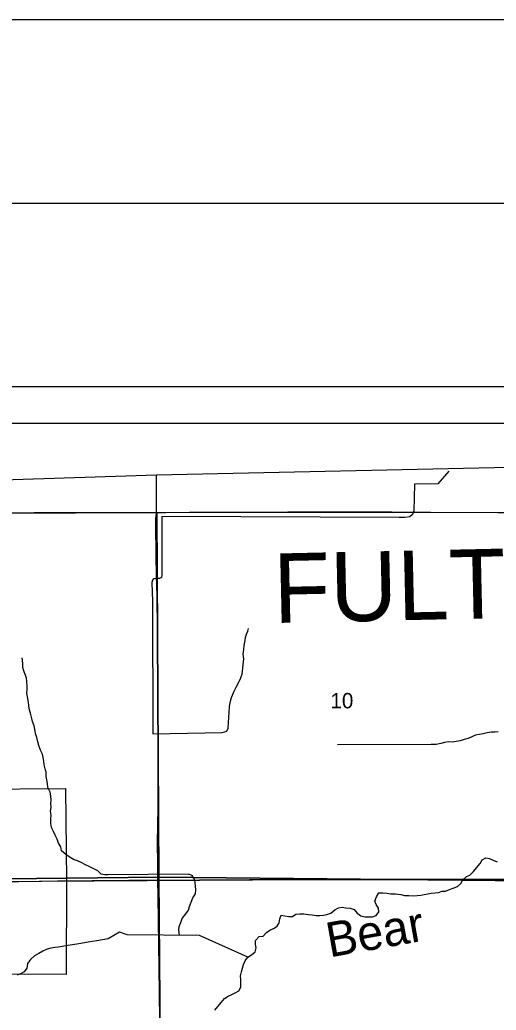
# Model space of a CAD drawing. Extents: x 0 to 34, y 0 to 22.
# Drawn here: x 4.098 to 5.396, y 19.3 to 22 of the extents above; entities that cross this region are included whole.
import ezdxf

# ---------------------------------------------------------------- set-up
doc = ezdxf.new("R2010")
doc.units = 0
for name, color, linetype in [('Default', 7, 'Continuous'), ('GM_X_Corporation', 7, 'Continuous'), ('GM_X_County_Text', 7, 'Continuous'), ('GM_X_Minor_River', 7, 'Continuous'), ('GM_X_Minor_River_Text', 7, 'Continuous'), ('GM_X_Rail_Line', 7, 'Continuous'), ('GM_X_Section', 7, 'Continuous'), ('GM_X_Section_Text', 7, 'Continuous'), ('GM_X_State_Route', 7, 'Continuous'), ('GM_X_Township_Road', 7, 'Continuous'), ('SH_Border', 7, 'Continuous'), ('SH_Cut_Line', 7, 'Continuous'), ('SH_Data', 7, 'Continuous')]:
    doc.layers.add(name, color=color, linetype=linetype)

msp = doc.modelspace()

# ---------------------------------------------------------------- linework, layer by layer
at = {"layer": 'Default'}
msp.add_lwpolyline([(5.4741, 20.7803), (4.4698, 20.7584), (3.7151, 20.7343)], dxfattribs=at)
at = {"layer": 'GM_X_Corporation'}
msp.add_lwpolyline([(3.155, 19.3995), (3.1598, 19.65), (3.0434, 19.6498), (3.0413, 19.9196), (3.1522, 19.9187), (3.151, 20.1523), (3.4671, 20.153), (3.72, 20.1538), (3.9709, 20.1548), (3.9717, 19.9024), (4.2217, 19.9047), (4.2244, 19.6529), (4.2237, 19.397), (3.7274, 19.3997), (3.2857, 19.3997)], close=True, dxfattribs=at)
at = {"layer": 'GM_X_Minor_River'}
for points in [[(5.2672, 20.7693), (5.2366, 20.7353), (5.1729, 20.7341), (5.171, 20.6616), (5.1678, 20.6514), (5.1609, 20.6446), (5.1469, 20.6436), (5.1313, 20.6434), (4.4846, 20.6459), (4.4848, 20.4862), (4.4835, 20.4794), (4.4786, 20.4771), (4.4721, 20.4764), (4.4619, 20.4758), (4.4588, 20.4724), (4.4569, 20.466), (4.4589, 20.4143), (4.4602, 20.0538), (4.6487, 20.0573), (4.6616, 20.061), (4.6651, 20.0685), (4.6691, 20.1266), (4.6708, 20.1387), (4.6744, 20.1527), (4.6821, 20.1701), (4.6876, 20.181), (4.6984, 20.2014), (4.7031, 20.2162), (4.7061, 20.2416), (4.7078, 20.2578), (4.7064, 20.2704), (4.7077, 20.2837), (4.7093, 20.2946), (4.7113, 20.3079), (4.713, 20.3159), (4.7157, 20.3249), (4.7188, 20.3329), (4.7208, 20.3404)], [(4.3373, 19.6688), (4.3294, 19.6688), (4.3195, 19.6712), (4.3098, 19.6796), (4.2977, 19.6866), (4.2868, 19.692), (4.2762, 19.6959), (4.2649, 19.7024), (4.2551, 19.7067), (4.2453, 19.7102), (4.2347, 19.716), (4.2231, 19.7241), (4.2114, 19.7345), (4.2089, 19.7451), (4.2029, 19.755), (4.1996, 19.7661), (4.1937, 19.7775), (4.1896, 19.7874), (4.1837, 19.7977), (4.1823, 19.8087), (4.182, 19.8209), (4.1829, 19.8315), (4.1811, 19.8425), (4.1828, 19.8528), (4.1821, 19.863), (4.1826, 19.8725), (4.182, 19.8843), (4.1806, 19.8941), (4.1743, 19.9075), (4.1729, 19.9181), (4.1711, 19.928), (4.1693, 19.9375), (4.169, 19.9485), (4.1665, 19.958), (4.1643, 19.9687), (4.1633, 19.9786), (4.1612, 19.9888), (4.159, 19.9983), (4.1542, 20.009), (4.1498, 20.0212), (4.1468, 20.0315), (4.1443, 20.0433), (4.1407, 20.0547), (4.1385, 20.0661), (4.1363, 20.0756), (4.1323, 20.0874), (4.129, 20.0992), (4.1265, 20.1095), (4.1232, 20.1216), (4.1222, 20.1319), (4.12, 20.1441), (4.1183, 20.1543), (4.1168, 20.1642), (4.1173, 20.1741), (4.1174, 20.1839), (4.1168, 20.1949), (4.1154, 20.2056), (4.1121, 20.2151), (4.1084, 20.225), (4.1059, 20.2345), (4.1056, 20.244), (4.105, 20.2539), (4.1043, 20.2603)], [(5.4015, 20.0586), (5.392, 20.058), (5.3822, 20.0577), (5.3716, 20.0559), (5.3605, 20.0537), (5.3495, 20.0516), (5.3393, 20.0498), (5.3297, 20.0453), (5.3191, 20.0409), (5.3088, 20.0379), (5.2978, 20.0342), (5.2871, 20.0328), (5.2754, 20.0303), (5.2648, 20.0315), (5.2549, 20.0294), (5.2454, 20.0268), (5.2324, 20.0242), (5.2184, 20.0244)], [(5.2184, 20.0244), (4.9633, 20.0235)], [(4.7073, 19.4241), (4.7116, 19.4343), (4.7193, 19.4445), (4.7288, 19.4508), (4.7388, 19.4591), (4.7415, 19.4697), (4.7401, 19.4803), (4.7402, 19.4902), (4.7498, 19.5011), (4.7605, 19.5018), (4.7697, 19.5119), (4.7792, 19.5183), (4.7887, 19.5224), (4.7987, 19.5287), (4.8048, 19.5385), (4.8061, 19.5491), (4.8096, 19.559), (4.8194, 19.5574), (4.8297, 19.555), (4.8403, 19.5556), (4.8498, 19.562), (4.8608, 19.5626), (4.8714, 19.5622), (4.8839, 19.5605), (4.8941, 19.5597), (4.9051, 19.5584), (4.915, 19.5579), (4.9248, 19.559), (4.9347, 19.5604), (4.9454, 19.5648), (4.9557, 19.5731), (4.9664, 19.5787), (4.9759, 19.5809), (4.9861, 19.5793), (4.9975, 19.5784), (5.0084, 19.5741), (5.0166, 19.5642), (5.0272, 19.5572), (5.0374, 19.5548), (5.0484, 19.554), (5.059, 19.5546), (5.0689, 19.5579), (5.0758, 19.5677), (5.0755, 19.578), (5.0688, 19.5879), (5.0648, 19.5975), (5.0698, 19.6092), (5.0756, 19.6201), (5.087, 19.6196), (5.098, 19.6191), (5.109, 19.6171), (5.1211, 19.6174), (5.1355, 19.615), (5.1457, 19.613), (5.1574, 19.6125), (5.1696, 19.612), (5.1809, 19.6123), (5.1904, 19.6133), (5.1999, 19.6155), (5.2094, 19.6173), (5.2189, 19.6187), (5.2295, 19.6197), (5.239, 19.6204), (5.2485, 19.6245), (5.258, 19.6248), (5.2683, 19.6292), (5.279, 19.6329), (5.29, 19.6374), (5.2999, 19.6452), (5.305, 19.6551), (5.3145, 19.6641), (5.3241, 19.6678), (5.3337, 19.6783), (5.3417, 19.6881), (5.3517, 19.6998), (5.3575, 19.7103), (5.3674, 19.7155), (5.3773, 19.7139), (5.3878, 19.7085), (5.3988, 19.7046)], [(4.5576, 19.6711), (4.3373, 19.6688)], [(4.5331, 19.5044), (4.5305, 19.5181), (4.5322, 19.5283), (4.5364, 19.5389), (4.5404, 19.5495), (4.55, 19.5623), (4.5569, 19.5725), (4.5604, 19.5827), (4.5647, 19.594), (4.5694, 19.6065), (4.576, 19.6174), (4.5772, 19.6277), (4.5762, 19.6379), (4.5752, 19.6478), (4.5738, 19.6573), (4.5674, 19.6668), (4.5576, 19.6711), (4.5584, 19.6707)], [(4.7193, 19.4445), (4.5876, 19.5038), (4.3901, 19.5058), (4.369, 19.5124), (4.3381, 19.4941), (4.3073, 19.4888), (4.2834, 19.4852), (4.2583, 19.4805), (4.2412, 19.478), (4.2287, 19.4759)], [(4.2287, 19.4759), (4.2021, 19.4719), (4.1926, 19.4709), (4.182, 19.4691), (4.1725, 19.4665), (4.1603, 19.461), (4.1492, 19.4543), (4.1374, 19.4479), (4.1271, 19.4378), (4.1186, 19.4268), (4.1166, 19.4147), (4.1093, 19.4046), (4.0997, 19.399), (4.0902, 19.3956)], [(4.6286, 19.2996), (4.6382, 19.3109), (4.6459, 19.3207), (4.6551, 19.3316), (4.6651, 19.3384), (4.6753, 19.3428), (4.6849, 19.3469), (4.6948, 19.3525), (4.7002, 19.3627), (4.6999, 19.3733), (4.6997, 19.3832), (4.699, 19.3938), (4.7018, 19.4044), (4.7042, 19.4143), (4.7073, 19.4241)]]:
    msp.add_lwpolyline(points, dxfattribs=at)
at = {"layer": 'GM_X_Rail_Line'}
msp.add_lwpolyline([(2.1, 19.6449), (2.4687, 19.6463), (3.2362, 19.6474), (3.7244, 19.6491), (5.0197, 19.6574), (5.4852, 19.6574), (5.5146, 19.6675), (5.5588, 19.7034), (6.1514, 20.0969), (6.291, 20.193), (6.3333, 20.2132), (6.3747, 20.2169), (6.4833, 20.2279), (7.4795, 20.3149), (8.1518, 20.3773), (8.7379, 20.4271), (8.9, 20.4441)], dxfattribs=at)
at = {"layer": 'GM_X_Section'}
for points in [[(3.4668, 20.6546), (4.4712, 20.6576), (4.4763, 19.663), (3.4763, 19.6515)], [(4.4712, 20.6576), (5.4752, 20.6568), (5.485, 19.653), (4.4763, 19.663)], [(3.4763, 19.6515), (4.4763, 19.663), (4.4846, 18.6535), (3.4848, 18.6515)], [(4.4763, 19.663), (5.485, 19.653), (5.4908, 18.6512), (4.4846, 18.6535)]]:
    msp.add_lwpolyline(points, close=True, dxfattribs=at)
at = {"layer": 'GM_X_State_Route'}
msp.add_line((4.2246, 19.6523), (4.2951, 19.6535), dxfattribs=at)
for points in [[(4.2951, 19.6535), (4.3041, 19.6537), (4.3943, 19.6544), (4.4739, 19.6545), (4.4751, 19.6545), (4.4844, 19.6546), (4.587, 19.6552), (4.7238, 19.6564), (4.7549, 19.6563), (4.8109, 19.6561), (4.8918, 19.6564), (4.9322, 19.6565), (4.9788, 19.6565), (5.0503, 19.6563), (5.1499, 19.6563), (5.268, 19.6558), (5.3147, 19.6556), (5.3644, 19.6555), (5.4639, 19.6552), (5.4733, 19.6556), (5.4796, 19.6563), (5.4853, 19.6574)], [(3.8287, 19.6496), (3.8448, 19.6497), (3.848, 19.6495), (3.8655, 19.6501), (3.9278, 19.65), (3.9331, 19.6501), (3.9808, 19.6505), (4.0053, 19.6504), (4.0235, 19.6504), (4.0263, 19.6503), (4.0295, 19.6505), (4.0354, 19.6505), (4.0366, 19.6505), (4.0945, 19.651), (4.1506, 19.6514), (4.2004, 19.6522), (4.2246, 19.6523)]]:
    msp.add_lwpolyline(points, dxfattribs=at)
at = {"layer": 'GM_X_Township_Road'}
for points in [[(4.4698, 20.657), (4.47, 20.675), (4.47, 20.7578)], [(3.7161, 20.6524), (3.8419, 20.6538), (3.9601, 20.6544), (4.0192, 20.655), (4.0534, 20.6552), (4.1187, 20.6558), (4.2494, 20.6561), (4.4048, 20.6565), (4.4698, 20.657)], [(4.4739, 19.6545), (4.474, 19.6754), (4.4733, 19.7127), (4.4732, 19.7437), (4.4731, 19.7561), (4.4739, 19.8027), (4.4742, 19.8524), (4.4742, 19.9051), (4.4743, 19.961), (4.4746, 20.0107), (4.4744, 20.0355), (4.4742, 20.1038), (4.4734, 20.2467), (4.4717, 20.4298), (4.4703, 20.4857), (4.469, 20.5385), (4.4683, 20.6254), (4.4687, 20.6376), (4.4693, 20.6495), (4.4698, 20.6539), (4.4698, 20.657)], [(4.4698, 20.657), (4.4951, 20.6572), (4.5604, 20.6574), (4.828, 20.6583), (4.8715, 20.6584), (4.9617, 20.6586), (5.0364, 20.6589), (5.1111, 20.6587), (5.2168, 20.658), (5.4003, 20.6572), (5.4761, 20.6568)], [(4.4843, 18.6526), (4.4841, 18.6577), (4.4843, 18.6637), (4.484, 18.6978), (4.4833, 18.7818), (4.4831, 18.7911), (4.4826, 18.8563), (4.4825, 18.9216), (4.482, 18.9745), (4.4816, 19.018), (4.4806, 19.1145), (4.4797, 19.2047), (4.478, 19.3446), (4.4772, 19.4162), (4.4766, 19.4784), (4.475, 19.609), (4.4739, 19.6545)]]:
    msp.add_lwpolyline(points, dxfattribs=at)
at = {"layer": 'SH_Border'}
msp.add_lwpolyline([(1.5, 21.5), (33.5, 21.5), (33.5, 0.5), (1.5, 0.5)], close=True, dxfattribs=at)
at = {"layer": 'SH_Cut_Line'}
for points in [[(0, 0), (34, 0), (34, 22), (0, 22)], [(2.1, 20.6957), (2.1, 14.1), (8.9, 14.1), (8.9, 20.8277), (8.6079, 20.8216), (7.476, 20.811), (6.4789, 20.8005), (5.4741, 20.7803), (4.4698, 20.7584), (3.7151, 20.7343), (2.4566, 20.7022)]]:
    msp.add_lwpolyline(points, close=True, dxfattribs=at)
at = {"layer": 'SH_Data'}
for p, q in [((2, 21), (9, 21)), ((2.1, 20.9), (8.9, 20.9))]:
    msp.add_line(p, q, dxfattribs=at)

# ---------------------------------------------------------------- texts
at = {"layer": 'GM_X_County_Text'}
msp.add_text('FULTON COUNTY', height=0.189394, rotation=1.2494, dxfattribs=at).set_placement((4.7905, 20.3554))
at = {"layer": 'GM_X_Minor_River_Text'}
msp.add_text('Bear', height=0.09476, rotation=10.1383, dxfattribs=at).set_placement((4.9417, 19.4435))
at = {"layer": 'GM_X_Section_Text'}
msp.add_text('10', height=0.04186, rotation=0, dxfattribs=at).set_placement((4.9442, 20.1229))

doc.saveas('drawing.dxf')
